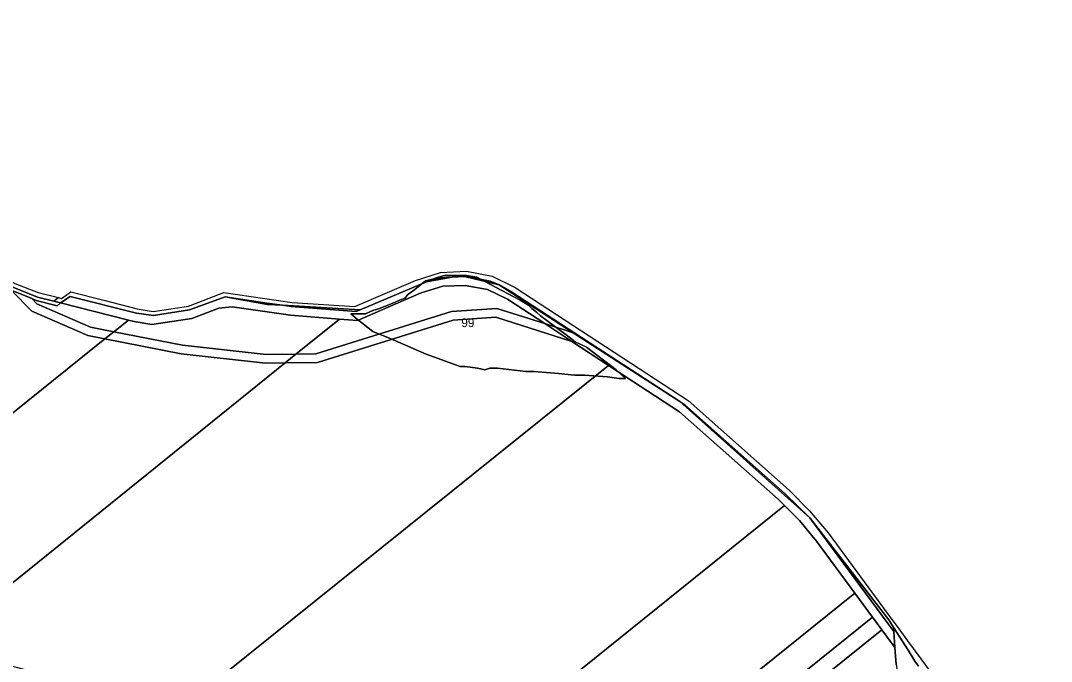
# Model space of a CAD drawing. Extents: x -541351 to -537540, y -1162694 to -1159725.
# Drawn here: x -538870 to -538279, y -1160383 to -1160016 of the extents above; entities that cross this region are included whole.
import ezdxf

# ---------------------------------------------------------------- set-up
doc = ezdxf.new("R2010")
doc.units = 0
for name, color, linetype in [('95560013', 7, 'Continuous'), ('95610013', 7, 'Continuous'), ('95630013', 7, 'Continuous'), ('95640013', 7, 'Continuous'), ('95660013', 7, 'Continuous')]:
    doc.layers.add(name, color=color, linetype=linetype)

msp = doc.modelspace()

# ---------------------------------------------------------------- linework, layer by layer
at = {"layer": '95560013'}
for points in [[(-538831.18, -1160196.34), (-538821.3, -1160198.29), (-539040.21, -1160374.33), (-539048.36, -1160373.06), (-539056.23, -1160370.78), (-539064.1, -1160367.35), (-539079.28, -1160354.4), (-539091.17, -1160343.7), (-538875.02, -1160170.41), (-538863.17, -1160182.34)], [(-538621.71, -1160187.61), (-538597.32, -1160185.88), (-538553.83, -1160199.69), (-538532.84, -1160213.45), (-538778.94, -1160411.23), (-538874.8, -1160385.7), (-538928.34, -1160381.56), (-538718.14, -1160212.05), (-538699.62, -1160211.88)], [(-538988.93, -1160377.95), (-539008.72, -1160374.73), (-539040.21, -1160374.33), (-538821.3, -1160198.29), (-538777.62, -1160206.88), (-538729.24, -1160212.16), (-538718.14, -1160212.05), (-538928.34, -1160381.56), (-538948.98, -1160379.96)], [(-538730.03, -1160424.25), (-538778.94, -1160411.23), (-538532.84, -1160213.45), (-538492.15, -1160240.13), (-538435.32, -1160290.29), (-538431.95, -1160293.68), (-538642.87, -1160463.48), (-538647.61, -1160461.1), (-538711.16, -1160429.21)], [(-538579.55, -1160495.26), (-538642.87, -1160463.48), (-538431.95, -1160293.68), (-538423.41, -1160302.27), (-538413.6, -1160314.15), (-538391.67, -1160343.95)], [(-538579.55, -1160495.26), (-538391.67, -1160343.95), (-538381.54, -1160357.72), (-538562.84, -1160503.65)], [(-538368.74, -1160375.12), (-538367.88, -1160384.77), (-538365.12, -1160401.34), (-538362.23, -1160412.05), (-538475.48, -1160503.12), (-538513.09, -1160533.06), (-538523.56, -1160523.26), (-538554.08, -1160508.04), (-538376.2, -1160364.97)]]:
    msp.add_lwpolyline(points, close=True, dxfattribs=at)
at = {"layer": '95610013'}
msp.add_lwpolyline([(-538381.54, -1160357.72), (-538376.2, -1160364.97), (-538554.08, -1160508.04), (-538562.84, -1160503.65)], close=True, dxfattribs=at)
at = {"layer": '95630013'}
for points in [[(-538355.12, -1160385.74), (-538357.25, -1160382.86), (-538361.16, -1160376.69), (-538369.3, -1160363.86), (-538372.22, -1160359.25), (-538417.44, -1160300.69), (-538431.51, -1160287), (-538488.99, -1160236.04), (-538491.9, -1160234.05), (-538588.1, -1160171.42), (-538595.44, -1160167.36), (-538600.64, -1160165.11), (-538614.24, -1160162.43), (-538615.23, -1160162.49), (-538617.34, -1160161.97), (-538622.38, -1160162.91), (-538628.81, -1160163.29), (-538637.02, -1160165.65), (-538675.11, -1160181.63), (-538719.64, -1160179.01), (-538728.6, -1160177.85), (-538752.52, -1160174.23), (-538772.82, -1160181.69), (-538793.6, -1160184.93), (-538803.32, -1160183.46), (-538841.31, -1160173.9), (-538846.77, -1160177.7), (-538850.66, -1160176.7), (-538848.02, -1160174.62), (-538846.13, -1160175.14), (-538840.94, -1160171.26), (-538822.03, -1160176.13), (-538802.78, -1160180.96), (-538793.68, -1160182.67), (-538773.4, -1160179.43), (-538753.21, -1160171.71), (-538714.09, -1160177.36), (-538678.11, -1160179.77), (-538643.45, -1160164.73), (-538629.14, -1160160.19), (-538614.23, -1160159.55), (-538599.49, -1160162.42), (-538586.2, -1160168.91), (-538487.18, -1160233.62), (-538429.21, -1160285.01), (-538417.52, -1160296.82), (-538407, -1160309.44), (-538370.49, -1160358.94), (-538366.89, -1160363.81), (-538361.36, -1160371.31), (-538357.11, -1160377.08), (-538279, -1160482.96)], [(-538874.16, -1160168.65), (-538859.9, -1160174.32), (-538850.66, -1160176.7), (-538846.77, -1160177.7), (-538848.8, -1160179.32), (-538860.75, -1160176.21), (-538863.2, -1160175.22), (-538875.02, -1160170.41)]]:
    msp.add_lwpolyline(points, dxfattribs=at)
for points in [[(-538628.81, -1160163.29), (-538622.38, -1160162.91), (-538637.02, -1160165.65)], [(-538600.64, -1160165.11), (-538595.44, -1160167.36), (-538615.23, -1160162.49), (-538614.24, -1160162.43)], [(-538491.9, -1160234.05), (-538552.96, -1160194.72), (-538595.44, -1160167.36), (-538588.1, -1160171.42)], [(-538728.21, -1160178.51), (-538752.52, -1160174.23), (-538728.6, -1160177.85), (-538719.64, -1160179.01)], [(-538431.51, -1160287), (-538417.44, -1160300.69), (-538491.9, -1160234.05), (-538488.99, -1160236.04)]]:
    msp.add_lwpolyline(points, close=True, dxfattribs=at)
at = {"layer": '95640013'}
for points in [[(-538848.02, -1160174.62), (-538850.66, -1160176.7), (-538859.9, -1160174.32), (-538874.16, -1160168.65), (-538886.36, -1160160.36), (-538955.06, -1160099.12), (-538967.47, -1160086.7), (-538978.16, -1160072.22), (-538986.31, -1160056.85), (-538992.36, -1160039.83), (-538998.75, -1160017.67), (-538996.64, -1160015.93), (-538990.06, -1160039.15), (-538984.11, -1160055.68), (-538975.92, -1160070.9), (-538965.59, -1160084.97), (-538953.46, -1160097.34), (-538885.01, -1160158.23), (-538872.92, -1160166.48), (-538859.62, -1160171.76)], [(-538719.64, -1160179.01), (-538714.61, -1160179.67), (-538677.35, -1160182.59), (-538675.11, -1160181.63), (-538637.02, -1160165.65), (-538622.38, -1160162.91), (-538615.23, -1160162.49), (-538595.44, -1160167.36), (-538552.96, -1160194.72), (-538569.34, -1160189.52), (-538590.58, -1160175.59), (-538602.1, -1160169.89), (-538614.9, -1160167.64), (-538627.79, -1160168.12), (-538640.22, -1160171.93), (-538676.56, -1160187.67), (-538686.92, -1160186.88), (-538715.07, -1160184.74), (-538748.5, -1160179.93), (-538756.08, -1160180.7), (-538771.58, -1160186.68), (-538794.49, -1160190.09), (-538804.53, -1160188.28), (-538807.83, -1160187.45), (-538846.77, -1160177.7), (-538841.31, -1160173.9), (-538803.32, -1160183.46), (-538793.6, -1160184.93), (-538772.82, -1160181.69), (-538752.52, -1160174.23), (-538728.21, -1160178.51)], [(-538622.38, -1160162.91), (-538617.34, -1160161.97), (-538615.23, -1160162.49)], [(-538863.2, -1160175.22), (-538860.3, -1160178.14), (-538829.68, -1160191.54), (-538816.21, -1160194.19), (-538821.3, -1160198.29), (-538831.18, -1160196.34), (-538863.17, -1160182.34), (-538875.02, -1160170.41)], [(-538602.1, -1160169.89), (-538590.58, -1160175.59), (-538569.34, -1160189.52), (-538596.72, -1160180.83), (-538622.65, -1160182.66), (-538700.4, -1160206.89), (-538711.86, -1160206.99), (-538686.92, -1160186.88), (-538676.56, -1160187.67), (-538640.22, -1160171.93), (-538627.79, -1160168.12), (-538614.9, -1160167.64)], [(-538848.8, -1160179.32), (-538846.77, -1160177.7), (-538807.83, -1160187.45), (-538816.21, -1160194.19), (-538829.68, -1160191.54), (-538860.3, -1160178.14), (-538863.2, -1160175.22), (-538860.75, -1160176.21)], [(-538776.87, -1160201.94), (-538816.21, -1160194.19), (-538807.83, -1160187.45), (-538804.53, -1160188.28), (-538794.49, -1160190.09), (-538771.58, -1160186.68), (-538756.08, -1160180.7), (-538748.5, -1160179.93), (-538715.07, -1160184.74), (-538686.92, -1160186.88), (-538711.86, -1160206.99), (-538728.99, -1160207.15)], [(-538677.35, -1160182.59), (-538714.61, -1160179.67), (-538719.64, -1160179.01), (-538675.11, -1160181.63)], [(-538711.86, -1160206.99), (-538700.4, -1160206.89), (-538622.65, -1160182.66), (-538596.72, -1160180.83), (-538569.34, -1160189.52), (-538553.83, -1160199.69), (-538597.32, -1160185.88), (-538621.71, -1160187.61), (-538699.62, -1160211.88), (-538718.14, -1160212.05)], [(-538569.34, -1160189.52), (-538552.96, -1160194.72), (-538491.9, -1160234.05), (-538417.44, -1160300.69), (-538369.19, -1160365.99), (-538368.74, -1160375.12), (-538376.2, -1160364.97), (-538381.54, -1160357.72), (-538391.67, -1160343.95), (-538413.6, -1160314.15), (-538423.41, -1160302.27), (-538431.95, -1160293.68), (-538435.32, -1160290.29), (-538492.15, -1160240.13), (-538532.84, -1160213.45), (-538553.83, -1160199.69)], [(-538728.99, -1160207.15), (-538711.86, -1160206.99), (-538718.14, -1160212.05), (-538729.24, -1160212.16), (-538777.62, -1160206.88), (-538821.3, -1160198.29), (-538816.21, -1160194.19), (-538776.87, -1160201.94)], [(-538369.19, -1160365.99), (-538417.44, -1160300.69), (-538372.22, -1160359.25), (-538369.3, -1160363.86)]]:
    msp.add_lwpolyline(points, close=True, dxfattribs=at)
msp.add_lwpolyline([(-538367.88, -1160384.77), (-538368.74, -1160375.12), (-538369.19, -1160365.99), (-538369.3, -1160363.86), (-538361.16, -1160376.69), (-538357.25, -1160382.86), (-538355.12, -1160385.74)], dxfattribs=at)
at = {"layer": '95660013'}
msp.add_lwpolyline([(-538872.92, -1160166.48), (-538859.62, -1160171.76), (-538848.02, -1160174.62), (-538846.13, -1160175.14), (-538840.94, -1160171.26), (-538822.03, -1160176.13), (-538802.78, -1160180.96), (-538793.68, -1160182.67), (-538773.4, -1160179.43), (-538753.21, -1160171.71), (-538714.09, -1160177.36), (-538678.11, -1160179.77), (-538643.45, -1160164.73), (-538629.14, -1160160.19), (-538614.23, -1160159.55), (-538599.49, -1160162.42), (-538586.2, -1160168.91), (-538487.18, -1160233.62), (-538429.21, -1160285.01), (-538417.52, -1160296.82), (-538407, -1160309.44), (-538370.49, -1160358.94), (-538366.89, -1160363.81), (-538361.36, -1160371.31), (-538357.11, -1160377.08), (-538279, -1160482.96)], dxfattribs=at)
for points in [[(-538637.31, -1160207), (-538617.81, -1160214), (-538614.87, -1160214), (-538607.87, -1160215), (-538603.62, -1160216), (-538600.69, -1160215), (-538596.31, -1160215), (-538580.12, -1160217), (-538575.31, -1160217), (-538561.37, -1160218), (-538552.31, -1160219), (-538546.5, -1160219), (-538533.37, -1160220), (-538526.87, -1160221), (-538523.12, -1160221), (-538528.37, -1160216), (-538545.31, -1160203), (-538551.81, -1160200), (-538557.12, -1160196), (-538571.81, -1160185), (-538574.12, -1160183), (-538576.66, -1160180.78), (-538578.69, -1160179), (-538583.31, -1160176), (-538600.81, -1160167), (-538608.31, -1160163), (-538614.19, -1160162), (-538617.69, -1160162), (-538622.87, -1160162), (-538626.81, -1160162), (-538630.12, -1160163), (-538633.62, -1160164), (-538637.62, -1160165), (-538643.81, -1160170), (-538648, -1160173), (-538649.37, -1160175), (-538652.5, -1160176), (-538656.81, -1160178), (-538664.62, -1160181), (-538667.87, -1160182), (-538672.12, -1160184), (-538680.5, -1160184), (-538676.87, -1160187), (-538667.81, -1160194), (-538657.87, -1160198)], [(-538545.31, -1160203), (-538528.37, -1160216), (-538523.12, -1160221), (-538526.87, -1160221), (-538533.37, -1160220), (-538546.5, -1160219), (-538552.31, -1160219), (-538561.37, -1160218), (-538575.31, -1160217), (-538580.12, -1160217), (-538596.31, -1160215), (-538600.69, -1160215), (-538603.62, -1160216), (-538607.87, -1160215), (-538614.87, -1160214), (-538617.81, -1160214), (-538637.31, -1160207), (-538657.87, -1160198), (-538667.81, -1160194), (-538676.87, -1160187), (-538680.5, -1160184), (-538672.12, -1160184), (-538667.87, -1160182), (-538664.62, -1160181), (-538656.81, -1160178), (-538652.5, -1160176), (-538649.37, -1160175), (-538648, -1160173), (-538643.81, -1160170), (-538637.62, -1160165), (-538633.62, -1160164), (-538630.12, -1160163), (-538626.81, -1160162), (-538622.87, -1160162), (-538617.69, -1160162), (-538614.19, -1160162), (-538608.31, -1160163), (-538600.81, -1160167), (-538583.31, -1160176), (-538578.69, -1160179), (-538576.66, -1160180.78), (-538574.12, -1160183), (-538571.81, -1160185), (-538557.12, -1160196), (-538551.81, -1160200)]]:
    msp.add_lwpolyline(points, close=True, dxfattribs=at)

# ---------------------------------------------------------------- texts
msp.add_text('99', height=5, rotation=360, dxfattribs=at).set_placement((-538617.09, -1160191.5))

doc.saveas('drawing.dxf')
